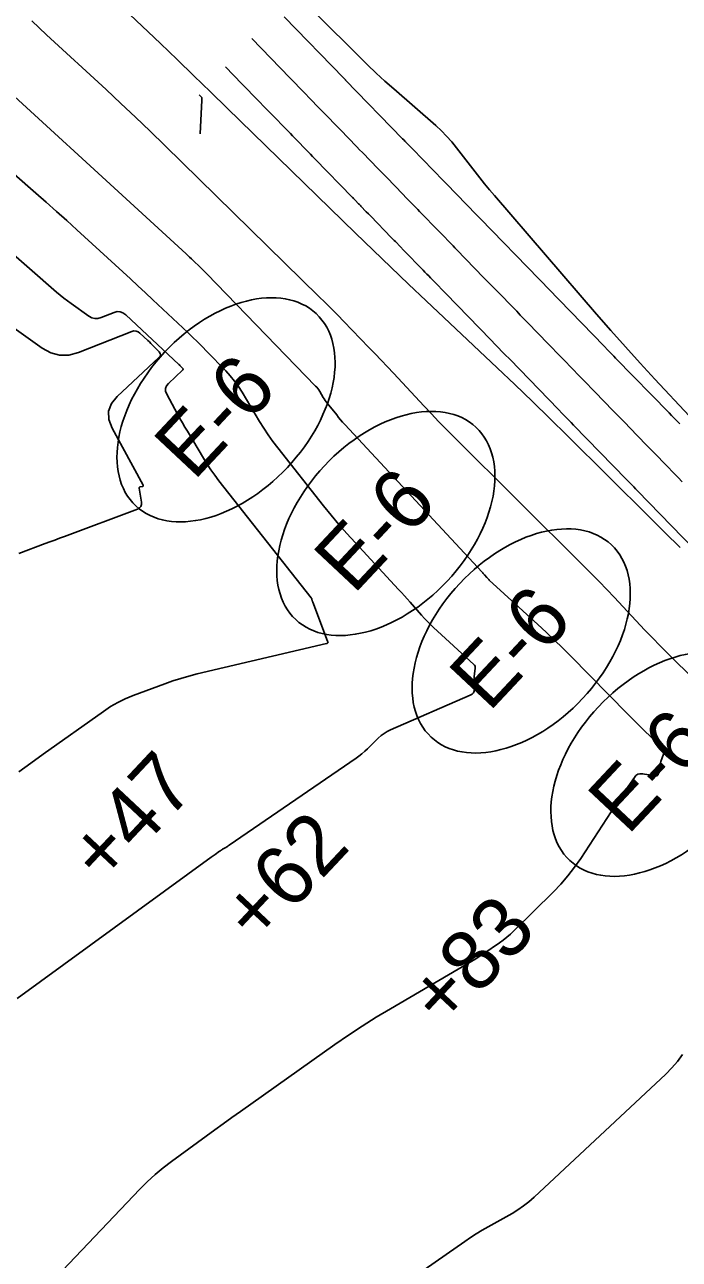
# Model space of a CAD drawing. Extents: x 1005228 to 1008882, y 1883389 to 1885754.
# Drawn here: x 1007015.2 to 1007083.3, y 1885273.6 to 1885401.9 of the extents above; entities that cross this region are included whole.
import ezdxf

# ---------------------------------------------------------------- set-up
doc = ezdxf.new("R2010")
doc.units = 0
for name, color, linetype in [('ATDIMS', 7, 'Continuous'), ('C-ANNO-NOTE', 7, 'Continuous'), ('R_Erosion', 7, 'Continuous'), ('S_BASELINE', 7, 'Continuous'), ('S_BRIDGE', 7, 'Continuous'), ('TSOBSTACLE', 7, 'Continuous')]:
    doc.layers.add(name, color=color, linetype=linetype)

msp = doc.modelspace()

# ---------------------------------------------------------------- linework, layer by layer
at = {"layer": 'ATDIMS'}
msp.add_lwpolyline([(1007033.44, 1885390.56), (1007033.64, 1885394.08), (1007033.64, 1885394.11), (1007033.64, 1885394.13), (1007033.64, 1885394.15), (1007033.64, 1885394.18), (1007033.64, 1885394.28), (1007033.64, 1885394.3), (1007033.64, 1885394.32), (1007033.63, 1885394.34), (1007033.61, 1885394.36), (1007033.35, 1885394.63)], dxfattribs=at)
at = {"layer": 'C-ANNO-NOTE'}
for points in [[(1007083.34, 1885347.59), (1007081.74, 1885349.16), (1007080.15, 1885350.73), (1007071.62, 1885359.21), (1007069.81, 1885360.99), (1007067.99, 1885362.76), (1007066.16, 1885364.52), (1007064.32, 1885366.26), (1007056.94, 1885373.23), (1007055.1, 1885374.97), (1007053.26, 1885376.72), (1007051.43, 1885378.48), (1007049.61, 1885380.25), (1007036.27, 1885393.26), (1007034.54, 1885394.94), (1007032.8, 1885396.62), (1007031.06, 1885398.29), (1007029.32, 1885399.96), (1007022.33, 1885406.62)], [(1007087.86, 1885357.45), (1007080.72, 1885365.09), (1007079.18, 1885366.76), (1007077.66, 1885368.44), (1007076.15, 1885370.13), (1007074.66, 1885371.84), (1007064.04, 1885384.16), (1007063.53, 1885384.76), (1007063.02, 1885385.38), (1007062.53, 1885385.99), (1007062.04, 1885386.62), (1007060.1, 1885389.13), (1007059.6, 1885389.74), (1007059.07, 1885390.33), (1007058.52, 1885390.89), (1007057.93, 1885391.43), (1007053.58, 1885395.24), (1007052.66, 1885396.06), (1007051.75, 1885396.89), (1007050.86, 1885397.74), (1007049.98, 1885398.6), (1007045.63, 1885402.93)], [(1007092.36, 1885326.56), (1007082.89, 1885335.75), (1007082.06, 1885336.56), (1007081.25, 1885337.37), (1007080.45, 1885338.2), (1007079.65, 1885339.03), (1007076.5, 1885342.4), (1007075.71, 1885343.23), (1007074.91, 1885344.06), (1007074.1, 1885344.89), (1007073.29, 1885345.7), (1007059.77, 1885359.14), (1007059, 1885359.92), (1007058.24, 1885360.7), (1007057.48, 1885361.48), (1007056.74, 1885362.28), (1007053.55, 1885365.7), (1007052.92, 1885366.38), (1007052.28, 1885367.05), (1007051.64, 1885367.73), (1007050.99, 1885368.39), (1007048.4, 1885371.06), (1007047.75, 1885371.72), (1007047.1, 1885372.38), (1007046.44, 1885373.04), (1007045.78, 1885373.69), (1007029.77, 1885389.38), (1007028.26, 1885390.85), (1007026.74, 1885392.3), (1007025.21, 1885393.74), (1007023.67, 1885395.18), (1007017.49, 1885400.88), (1007015.94, 1885402.31)], [(1007017.14, 1885270.34), (1007027.17, 1885280.9), (1007027.95, 1885281.68), (1007028.76, 1885282.43), (1007029.6, 1885283.13), (1007030.48, 1885283.8), (1007034.06, 1885286.41), (1007034.96, 1885287.06), (1007035.86, 1885287.71), (1007036.76, 1885288.35), (1007037.66, 1885288.99), (1007047.44, 1885295.93), (1007048.86, 1885296.91), (1007050.29, 1885297.86), (1007051.74, 1885298.77), (1007053.22, 1885299.65), (1007061.28, 1885304.35), (1007061.7, 1885304.6), (1007062.12, 1885304.86), (1007062.53, 1885305.13), (1007062.93, 1885305.4), (1007064.55, 1885306.51), (1007064.94, 1885306.79), (1007065.32, 1885307.09), (1007065.69, 1885307.41), (1007066.05, 1885307.75), (1007070.17, 1885311.81), (1007070.95, 1885312.62), (1007071.68, 1885313.47), (1007072.37, 1885314.36), (1007073.01, 1885315.28), (1007076.61, 1885320.8), (1007076.83, 1885321.14), (1007077.06, 1885321.48), (1007077.28, 1885321.81), (1007077.51, 1885322.15), (1007078.58, 1885323.7), (1007078.75, 1885323.89), (1007078.94, 1885324.02), (1007079.17, 1885324.08), (1007079.43, 1885324.07), (1007080.74, 1885323.85), (1007080.88, 1885323.85), (1007080.98, 1885323.89), (1007081.05, 1885323.98), (1007081.09, 1885324.12), (1007081.18, 1885324.75), (1007081.2, 1885324.9), (1007081.24, 1885325.06), (1007081.28, 1885325.21), (1007081.33, 1885325.36), (1007081.62, 1885326.11), (1007081.66, 1885326.28), (1007081.65, 1885326.43), (1007081.59, 1885326.58), (1007081.49, 1885326.72), (1007079.44, 1885328.74), (1007079.05, 1885329.12), (1007078.67, 1885329.5), (1007078.28, 1885329.89), (1007077.9, 1885330.27), (1007071.94, 1885336.32), (1007071.11, 1885337.15), (1007070.27, 1885337.97), (1007069.42, 1885338.78), (1007068.56, 1885339.58), (1007063.5, 1885344.21), (1007063.44, 1885344.28), (1007063.37, 1885344.34), (1007063.31, 1885344.41), (1007063.25, 1885344.48), (1007063, 1885344.75), (1007062.94, 1885344.82), (1007062.88, 1885344.89), (1007062.82, 1885344.96), (1007062.76, 1885345.03), (1007048.48, 1885360.38), (1007048.26, 1885360.61), (1007048.05, 1885360.86), (1007047.84, 1885361.1), (1007047.64, 1885361.36), (1007046.66, 1885362.6), (1007046.55, 1885362.74), (1007046.45, 1885362.88), (1007046.35, 1885363.03), (1007046.25, 1885363.19), (1007045.88, 1885363.81), (1007045.79, 1885363.96), (1007045.68, 1885364.1), (1007045.57, 1885364.24), (1007045.45, 1885364.37), (1007034.15, 1885376.03), (1007033.98, 1885376.21), (1007033.8, 1885376.38), (1007033.62, 1885376.56), (1007033.44, 1885376.73), (1007032.72, 1885377.41), (1007032.54, 1885377.58), (1007032.35, 1885377.75), (1007032.17, 1885377.92), (1007031.99, 1885378.09), (1007007.48, 1885400.56)], [(1007004.46, 1885386.41), (1007018.52, 1885374.14), (1007018.89, 1885373.82), (1007019.27, 1885373.51), (1007019.66, 1885373.21), (1007020.06, 1885372.93), (1007021.88, 1885371.64), (1007022.18, 1885371.47), (1007022.5, 1885371.39), (1007022.82, 1885371.39), (1007023.15, 1885371.48), (1007024.5, 1885372.01), (1007024.83, 1885372.1), (1007025.14, 1885372.09), (1007025.43, 1885371.98), (1007025.71, 1885371.78), (1007031.24, 1885366.61), (1007031.29, 1885366.56), (1007031.34, 1885366.51), (1007031.39, 1885366.46), (1007031.44, 1885366.41), (1007031.63, 1885366.21), (1007031.67, 1885366.16), (1007031.68, 1885366.11), (1007031.66, 1885366.06), (1007031.63, 1885366.01), (1007030.16, 1885364.64), (1007029.95, 1885364.39), (1007029.86, 1885364.12), (1007029.86, 1885363.83), (1007029.98, 1885363.53), (1007031.1, 1885361.45), (1007031.35, 1885361), (1007031.6, 1885360.56), (1007031.86, 1885360.11), (1007032.12, 1885359.67), (1007033.79, 1885356.87), (1007034.17, 1885356.26), (1007034.56, 1885355.67), (1007034.98, 1885355.09), (1007035.41, 1885354.52), (1007045, 1885342.37), (1007045.02, 1885342.34), (1007045.04, 1885342.3), (1007045.06, 1885342.27), (1007045.07, 1885342.23), (1007045.11, 1885342.06), (1007045.12, 1885342.02), (1007045.13, 1885341.98), (1007045.14, 1885341.94), (1007045.15, 1885341.9), (1007046.7, 1885337.85), (1007046.71, 1885337.83), (1007046.71, 1885337.82), (1007046.72, 1885337.81), (1007046.72, 1885337.79), (1007046.74, 1885337.72), (1007046.74, 1885337.71), (1007046.74, 1885337.71), (1007046.73, 1885337.7), (1007046.73, 1885337.7), (1007046.7, 1885337.67), (1007046.69, 1885337.67), (1007046.68, 1885337.66), (1007046.64, 1885337.63), (1007046.63, 1885337.62), (1007046.62, 1885337.62), (1007046.61, 1885337.61), (1007046.6, 1885337.61), (1007033.14, 1885334.45), (1007032.29, 1885334.23), (1007031.45, 1885333.99), (1007030.61, 1885333.72), (1007029.78, 1885333.43), (1007026.48, 1885332.2), (1007025.67, 1885331.86), (1007024.89, 1885331.48), (1007024.13, 1885331.05), (1007023.4, 1885330.56), (1007017.15, 1885326.11), (1007015.87, 1885325.19), (1007014.6, 1885324.27)], [(1007014.62, 1885346.97), (1007017.33, 1885347.99), (1007017.84, 1885348.17), (1007018.34, 1885348.36), (1007018.85, 1885348.55), (1007019.36, 1885348.74), (1007026.95, 1885351.59), (1007027.16, 1885351.71), (1007027.3, 1885351.86), (1007027.36, 1885352.06), (1007027.36, 1885352.3), (1007027.12, 1885353.76), (1007027.12, 1885353.81), (1007027.14, 1885353.85), (1007027.17, 1885353.88), (1007027.22, 1885353.89), (1007027.46, 1885353.93), (1007027.5, 1885353.94), (1007027.53, 1885353.97), (1007027.54, 1885354), (1007027.52, 1885354.05), (1007024.3, 1885359.99), (1007023.96, 1885360.89), (1007023.94, 1885361.74), (1007024.23, 1885362.54), (1007024.84, 1885363.29), (1007029.17, 1885367.33), (1007029.28, 1885367.47), (1007029.32, 1885367.62), (1007029.29, 1885367.76), (1007029.18, 1885367.91), (1007028.61, 1885368.51), (1007028.47, 1885368.66), (1007028.32, 1885368.8), (1007028.17, 1885368.95), (1007028.02, 1885369.09), (1007027.19, 1885369.87), (1007027, 1885370.01), (1007026.79, 1885370.08), (1007026.57, 1885370.09), (1007026.34, 1885370.03), (1007020.8, 1885367.85), (1007019.81, 1885367.59), (1007018.85, 1885367.57), (1007017.93, 1885367.82), (1007017.03, 1885368.31), (1007011.18, 1885372.45)], [(1007055.95, 1885271.96), (1007060.96, 1885275.48), (1007061.55, 1885275.88), (1007062.15, 1885276.26), (1007062.76, 1885276.64), (1007063.38, 1885276.99), (1007065.87, 1885278.39), (1007066.48, 1885278.75), (1007067.06, 1885279.16), (1007067.62, 1885279.59), (1007068.15, 1885280.06), (1007081.86, 1885292.86), (1007082.49, 1885293.5), (1007083.07, 1885294.18), (1007083.59, 1885294.91)]]:
    msp.add_lwpolyline(points, dxfattribs=at)
at = {"layer": 'R_Erosion'}
for centre in [(1007036.14, 1885361.9), (1007052.75, 1885350.09), (1007066.82, 1885337.88), (1007081.24, 1885325.06)]:
    msp.add_ellipse(centre, major_axis=(9.37, 9.99), ratio=0.638788, dxfattribs=at)
at = {"layer": 'S_BRIDGE'}
msp.add_lwpolyline([(1007014.44, 1885300.72), (1007034.6, 1885315.4), (1007034.7, 1885315.48), (1007034.8, 1885315.55), (1007034.91, 1885315.62), (1007035.01, 1885315.7), (1007035.46, 1885316.02), (1007035.55, 1885316.08), (1007035.63, 1885316.13), (1007035.71, 1885316.18), (1007035.79, 1885316.23), (1007036.13, 1885316.43), (1007036.22, 1885316.48), (1007036.3, 1885316.53), (1007036.38, 1885316.58), (1007036.46, 1885316.64), (1007049.65, 1885325.69), (1007049.96, 1885325.92), (1007050.27, 1885326.16), (1007050.57, 1885326.42), (1007050.85, 1885326.68), (1007051.97, 1885327.78), (1007052.25, 1885328.04), (1007052.56, 1885328.27), (1007052.89, 1885328.47), (1007053.24, 1885328.65), (1007061.53, 1885332.24), (1007061.71, 1885332.35), (1007061.85, 1885332.49), (1007061.92, 1885332.67), (1007061.95, 1885332.89), (1007061.93, 1885334.01), (1007061.93, 1885334.14), (1007061.94, 1885334.26), (1007061.95, 1885334.39), (1007061.96, 1885334.51), (1007062.04, 1885335.02), (1007062.05, 1885335.14), (1007062.02, 1885335.25), (1007061.97, 1885335.35), (1007061.89, 1885335.44), (1007057.71, 1885339.28), (1007057.38, 1885339.58), (1007057.07, 1885339.9), (1007056.76, 1885340.22), (1007056.46, 1885340.56), (1007055.27, 1885341.91), (1007054.98, 1885342.24), (1007054.68, 1885342.58), (1007054.38, 1885342.91), (1007054.07, 1885343.24), (1007049.55, 1885348.1), (1007048.7, 1885349.03), (1007047.87, 1885349.98), (1007047.06, 1885350.94), (1007046.27, 1885351.92), (1007041.51, 1885357.96), (1007041, 1885358.62), (1007040.53, 1885359.29), (1007040.07, 1885359.98), (1007039.63, 1885360.68), (1007037.81, 1885363.73), (1007037.43, 1885364.32), (1007037.02, 1885364.89), (1007036.58, 1885365.43), (1007036.11, 1885365.94), (1007034.16, 1885367.96), (1007033.67, 1885368.46), (1007033.18, 1885368.95), (1007032.67, 1885369.44), (1007032.17, 1885369.92), (1007028.54, 1885373.33), (1007027.76, 1885374.06), (1007026.98, 1885374.78), (1007026.2, 1885375.5), (1007025.42, 1885376.22), (1007020.65, 1885380.59), (1007019.6, 1885381.56), (1007018.53, 1885382.52), (1007017.46, 1885383.47), (1007016.39, 1885384.41), (1007004.25, 1885395)], dxfattribs=at)
at = {"layer": 'TSOBSTACLE'}
for points in [[(1007042.17, 1885402.75), (1007048.37, 1885396.37), (1007048.55, 1885396.19), (1007048.57, 1885396.17), (1007054.49, 1885390.07), (1007054.62, 1885389.94), (1007054.74, 1885389.81), (1007054.78, 1885389.78), (1007054.81, 1885389.74), (1007054.84, 1885389.71), (1007054.87, 1885389.68), (1007055.48, 1885389.06), (1007055.51, 1885389.02), (1007058.75, 1885385.68), (1007058.97, 1885385.46), (1007059.04, 1885385.39), (1007062.19, 1885382.15), (1007062.45, 1885381.88), (1007062.54, 1885381.79), (1007068.67, 1885375.47), (1007068.99, 1885375.15), (1007069.54, 1885374.58), (1007069.62, 1885374.5), (1007075.43, 1885368.52), (1007075.83, 1885368.1), (1007076.43, 1885367.48), (1007076.63, 1885367.28), (1007082.18, 1885361.57), (1007082.43, 1885361.32), (1007082.67, 1885361.06), (1007083.29, 1885360.43)], [(1007083.55, 1885354.43), (1007083.14, 1885354.85), (1007081.5, 1885356.54), (1007081.08, 1885356.96), (1007080.67, 1885357.39), (1007080.26, 1885357.81), (1007079.85, 1885358.23), (1007078.08, 1885360.06), (1007077.65, 1885360.5), (1007077.21, 1885360.95), (1007076.78, 1885361.39), (1007076.35, 1885361.84), (1007074.51, 1885363.73), (1007074.1, 1885364.15), (1007073.7, 1885364.57), (1007073.29, 1885364.98), (1007072.89, 1885365.4), (1007071.27, 1885367.07), (1007070.87, 1885367.48), (1007070.46, 1885367.9), (1007070.06, 1885368.31), (1007069.65, 1885368.73), (1007067.48, 1885370.97), (1007067.1, 1885371.36), (1007066.72, 1885371.75), (1007066.35, 1885372.14), (1007065.97, 1885372.52), (1007064.46, 1885374.08), (1007064.08, 1885374.47), (1007063.7, 1885374.86), (1007063.32, 1885375.24), (1007062.95, 1885375.63), (1007060.11, 1885378.56), (1007059.93, 1885378.74), (1007059.75, 1885378.93), (1007059.57, 1885379.11), (1007059.39, 1885379.3), (1007058.67, 1885380.03), (1007058.31, 1885380.4), (1007057.95, 1885380.77), (1007056.6, 1885382.16), (1007056.43, 1885382.34), (1007056.26, 1885382.52), (1007056.09, 1885382.7), (1007055.91, 1885382.87), (1007055.22, 1885383.58), (1007054.88, 1885383.94), (1007054.53, 1885384.3), (1007052.84, 1885386.04), (1007052.81, 1885386.07), (1007052.77, 1885386.11), (1007052.74, 1885386.14), (1007052.7, 1885386.18), (1007052.53, 1885386.35), (1007052.43, 1885386.46), (1007052.18, 1885386.71), (1007052.13, 1885386.77), (1007052.07, 1885386.82), (1007052.02, 1885386.88), (1007051.97, 1885386.93), (1007050.32, 1885388.63), (1007050.02, 1885388.93), (1007049.73, 1885389.24), (1007049.44, 1885389.54), (1007049.15, 1885389.84), (1007046.4, 1885392.67), (1007046.1, 1885392.98), (1007045.8, 1885393.29), (1007045.49, 1885393.6), (1007045.19, 1885393.91), (1007043.98, 1885395.15), (1007043.68, 1885395.46), (1007043.38, 1885395.78), (1007043.08, 1885396.09), (1007042.78, 1885396.4), (1007038.82, 1885400.47)], [(1007084.79, 1885347.41), (1007078.89, 1885353.49), (1007078.7, 1885353.68), (1007078.51, 1885353.88), (1007077.94, 1885354.47), (1007077.75, 1885354.66), (1007072.26, 1885360.31), (1007072, 1885360.58), (1007071.74, 1885360.85), (1007071.09, 1885361.51), (1007070.7, 1885361.92), (1007065.62, 1885367.15), (1007065.13, 1885367.65), (1007064.15, 1885368.66), (1007063.66, 1885369.17), (1007058.97, 1885374), (1007058.58, 1885374.4), (1007058.18, 1885374.8), (1007057.4, 1885375.61), (1007057.21, 1885375.81), (1007057.01, 1885376.01), (1007056.82, 1885376.21), (1007056.62, 1885376.41), (1007054.59, 1885378.5), (1007054.27, 1885378.83), (1007053.74, 1885379.38), (1007053.63, 1885379.49), (1007053.52, 1885379.6), (1007053.42, 1885379.71), (1007053.31, 1885379.82), (1007051.18, 1885382.01), (1007050.95, 1885382.25), (1007050.72, 1885382.48), (1007050.16, 1885383.06), (1007050.1, 1885383.12), (1007050.04, 1885383.19), (1007049.97, 1885383.26), (1007049.91, 1885383.32), (1007049.57, 1885383.67), (1007049.48, 1885383.76), (1007049.38, 1885383.86), (1007049.34, 1885383.91), (1007049.29, 1885383.95), (1007045.37, 1885387.99), (1007045.14, 1885388.23), (1007044.91, 1885388.46), (1007044.68, 1885388.7), (1007044.45, 1885388.94), (1007043.52, 1885389.89), (1007043.29, 1885390.13), (1007043.06, 1885390.37), (1007042.83, 1885390.61), (1007042.6, 1885390.85), (1007038.94, 1885394.61), (1007038.37, 1885395.2), (1007037.8, 1885395.79), (1007036.08, 1885397.55)]]:
    msp.add_lwpolyline(points, dxfattribs=at)

# ---------------------------------------------------------------- texts
at = {"layer": 'R_Erosion'}
for p in [(1007032.78, 1885354.42), (1007049.39, 1885342.61), (1007063.46, 1885330.39), (1007077.87, 1885317.58)]:
    msp.add_text('E-6', height=6.25, rotation=46.8499, dxfattribs=at).set_placement(p)
at = {"layer": 'S_BASELINE'}
for s, p in [('+47', (1007023.59, 1885312.23)), ('+62', (1007039.51, 1885306.05)), ('+83', (1007058.92, 1885297.36))]:
    msp.add_text(s, height=6.25, rotation=46.8499, dxfattribs=at).set_placement(p)

doc.saveas('drawing.dxf')
